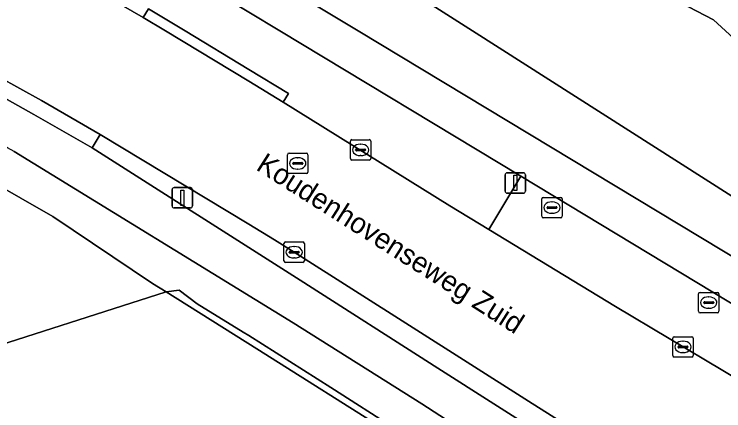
# Model space of a CAD drawing. Extents: x 162879 to 165540, y 384011 to 385181.
# Drawn here: x 163988.52 to 164023.23, y 384481.4 to 384500.81 of the extents above; entities that cross this region are included whole.
import ezdxf

# ---------------------------------------------------------------- set-up
doc = ezdxf.new("R2010")
doc.units = 0
for name, color, linetype in [('IMGEO_Erf', 7, 'Continuous'), ('IMGEO_Fietspad_gesloten', 7, 'Continuous'), ('IMGEO_Fietspad_open', 7, 'Continuous'), ('IMGEO_Gemengd_bos', 7, 'Continuous'), ('IMGEO_Groenvoorziening', 7, 'Continuous'), ('IMGEO_Hek', 7, 'Continuous'), ('IMGEO_Kolk', 7, 'Continuous'), ('IMGEO_Lichtmast', 7, 'Continuous'), ('IMGEO_Openbare_ruimte_label', 7, 'Continuous'), ('IMGEO_Pand', 7, 'Continuous'), ('IMGEO_Rijbaan_lokaal_gesloten', 7, 'Continuous'), ('IMGEO_Rioolput', 7, 'Continuous'), ('IMGEO_Verkeerseiland_open', 7, 'Continuous'), ('IMGEO_Verkeersregelinstallatiepaal', 7, 'Continuous'), ('IMGEO_Voetpad_open', 7, 'Continuous')]:
    doc.layers.add(name, color=color, linetype=linetype)

msp = doc.modelspace()

# ---------------------------------------------------------------- linework, layer by layer
at = {"layer": 'IMGEO_Erf'}
for points in [[(163977.102, 384518.017), (163999.855, 384507.078), (164000, 384506.985), (164010.947, 384500), (164040.047, 384481.433)], [(164075.059, 384483.197), (164073.692, 384484.761), (164077.391, 384488.124), (164071.515, 384492.449), (164068.483, 384490.058), (164069.655, 384486.192), (164069.193, 384486.039), (164069.32, 384485.578), (164065.977, 384484.533), (164065.378, 384486.451), (164059.412, 384484.592), (164050.462, 384484.232), (164041.668, 384486.233), (164033.747, 384490.379), (164023.311, 384500), (164022.729, 384500.537), (164017.458, 384503.291)], [(164024.324, 384464.783), (164007.922, 384479.696), (164007.065, 384480.235), (164000.388, 384484.433), (163995.958, 384487.218), (163986.076, 384484.053), (163967.218, 384478.066), (163952.026, 384473.244)]]:
    msp.add_lwpolyline(points, dxfattribs=at)
at = {"layer": 'IMGEO_Fietspad_gesloten'}
for points in [[(164038.87, 384479.774), (164005.351, 384500), (164000, 384503.229), (163995.542, 384505.919)], [(163992.18, 384505.608), (163994.613, 384504.172), (164000, 384500.919), (164001.522, 384500), (164013.311, 384492.88), (164028.96, 384483.428), (164037.825, 384478.074)]]:
    msp.add_lwpolyline(points, dxfattribs=at)
at = {"layer": 'IMGEO_Fietspad_open'}
for points in [[(164046.321, 384458.236), (164042.366, 384461.222), (164038.409, 384464.101), (164035.588, 384466.084), (164032.884, 384467.984), (164023.539, 384474.332), (164017.469, 384478.249), (164009.245, 384483.486), (164002.517, 384487.804), (163992.332, 384494.269), (163989.491, 384495.908), (163987.373, 384497.08), (163985.254, 384498.25), (163981.926, 384500), (163973.063, 384504.482), (163968.811, 384506.572), (163936.739, 384522.254)], [(163988.523, 384494.089), (164002.175, 384485.703), (164008.463, 384481.739), (164014.169, 384478.04), (164019.234, 384474.701), (164024.613, 384471.195), (164033.02, 384465.475), (164033.514, 384465.131), (164034.007, 384464.787)]]:
    msp.add_lwpolyline(points, dxfattribs=at)
msp.add_arc((163856.777, 384268.47), 261.268, 59.71804, 62.39691, dxfattribs=at)
at = {"layer": 'IMGEO_Gemengd_bos'}
msp.add_lwpolyline([(163943.494, 384482.414), (163944.929, 384476.199), (163938.963, 384474.249), (163933.363, 384469.485), (163922.095, 384461.981), (163922.323, 384455.925), (163952.519, 384470.865), (163953.09, 384471.066), (163952.736, 384471.79), (163952.026, 384473.244), (163967.218, 384478.066), (163986.076, 384484.053), (163995.958, 384487.218), (163995.289, 384487.639), (163990.412, 384490.908), (163987.273, 384492.711), (163977.777, 384489.802), (163954.868, 384485.471)], close=True, dxfattribs=at)
at = {"layer": 'IMGEO_Groenvoorziening'}
msp.add_lwpolyline([(164000, 384485.086), (163999.731, 384485.257), (163997.466, 384486.631), (163996.593, 384487.314), (163995.958, 384487.218), (164000.388, 384484.433), (164007.065, 384480.235), (164007.231, 384480.492), (164004.004, 384482.542)], close=True, dxfattribs=at)
at = {"layer": 'IMGEO_Hek'}
msp.add_lwpolyline([(163986.076, 384484.053), (163995.958, 384487.218)], dxfattribs=at)
at = {"layer": 'IMGEO_Kolk'}
for p, q in [((164005.042, 384494.673), (164005.894, 384494.673)), ((164004.967, 384493.747), (164004.967, 384494.599)), ((164005.455, 384494.453), (164005.48, 384494.453)), ((164005.968, 384494.599), (164005.968, 384493.747)), ((164005.226, 384494.167), (164005.226, 384494.179)), ((164005.664, 384494.13), (164005.266, 384494.13)), ((164005.269, 384494.216), (164005.667, 384494.216)), ((164005.71, 384494.179), (164005.71, 384494.167)), ((164005.894, 384493.673), (164005.042, 384493.673)), ((164005.478, 384493.893), (164005.453, 384493.893)), ((164014.405, 384491.848), (164015.257, 384491.848)), ((164014.33, 384490.922), (164014.33, 384491.774)), ((164014.818, 384491.628), (164014.843, 384491.628)), ((164015.331, 384491.774), (164015.331, 384490.922)), ((164014.589, 384491.342), (164014.589, 384491.354)), ((164015.027, 384491.305), (164014.629, 384491.305)), ((164014.632, 384491.391), (164015.03, 384491.391)), ((164015.073, 384491.354), (164015.073, 384491.342)), ((164015.257, 384490.848), (164014.405, 384490.848)), ((164014.841, 384491.068), (164014.816, 384491.068)), ((164001.718, 384488.739), (164001.718, 384489.591)), ((164001.793, 384489.665), (164002.645, 384489.665)), ((164002.206, 384489.445), (164002.231, 384489.445)), ((164002.719, 384489.591), (164002.719, 384488.739)), ((164001.977, 384489.159), (164001.977, 384489.171)), ((164002.415, 384489.122), (164002.017, 384489.122)), ((164002.02, 384489.208), (164002.418, 384489.208)), ((164002.461, 384489.171), (164002.461, 384489.159)), ((164002.229, 384488.885), (164002.204, 384488.885)), ((164002.645, 384488.665), (164001.793, 384488.665)), ((164021.996, 384486.273), (164021.996, 384487.125)), ((164022.071, 384487.199), (164022.923, 384487.199)), ((164022.997, 384487.125), (164022.997, 384486.273)), ((164022.255, 384486.693), (164022.255, 384486.705)), ((164022.693, 384486.656), (164022.295, 384486.656)), ((164022.298, 384486.742), (164022.696, 384486.742)), ((164022.484, 384486.979), (164022.509, 384486.979)), ((164022.739, 384486.705), (164022.739, 384486.693)), ((164022.507, 384486.419), (164022.482, 384486.419)), ((164022.923, 384486.199), (164022.071, 384486.199)), ((164020.736, 384484.105), (164020.736, 384484.957)), ((164020.811, 384485.031), (164021.663, 384485.031)), ((164021.737, 384484.957), (164021.737, 384484.105)), ((164021.038, 384484.574), (164021.436, 384484.574)), ((164021.224, 384484.811), (164021.249, 384484.811)), ((164020.995, 384484.525), (164020.995, 384484.537)), ((164021.433, 384484.488), (164021.035, 384484.488)), ((164021.247, 384484.251), (164021.222, 384484.251)), ((164021.479, 384484.537), (164021.479, 384484.525)), ((164021.663, 384484.031), (164020.811, 384484.031))]:
    msp.add_line(p, q, dxfattribs=at)
for points in [[(164005.042, 384494.673), (164005.894, 384494.673)], [(164004.967, 384493.747), (164004.967, 384494.599)], [(164005.968, 384494.599), (164005.968, 384493.747)], [(164005.894, 384493.673), (164005.042, 384493.673)], [(164014.405, 384491.848), (164015.257, 384491.848)], [(164014.33, 384490.922), (164014.33, 384491.774)], [(164015.331, 384491.774), (164015.331, 384490.922)], [(164015.257, 384490.848), (164014.405, 384490.848)], [(164001.718, 384488.739), (164001.718, 384489.591)], [(164001.793, 384489.665), (164002.645, 384489.665)], [(164002.719, 384489.591), (164002.719, 384488.739)], [(164002.645, 384488.665), (164001.793, 384488.665)], [(164021.996, 384486.273), (164021.996, 384487.125)], [(164022.071, 384487.199), (164022.923, 384487.199)], [(164022.997, 384487.125), (164022.997, 384486.273)], [(164022.923, 384486.199), (164022.071, 384486.199)], [(164020.736, 384484.105), (164020.736, 384484.957)], [(164020.811, 384485.031), (164021.663, 384485.031)], [(164021.737, 384484.957), (164021.737, 384484.105)], [(164021.663, 384484.031), (164020.811, 384484.031)]]:
    msp.add_lwpolyline(points, dxfattribs=at)
for centre, radius, start, end in [((164005.044, 384494.597), 0.0765, 91.552, 178.448), ((164005.044, 384494.597), 0.0765, 91.552, 178.448), ((164005.892, 384494.597), 0.0765, 1.552, 88.448), ((164005.892, 384494.597), 0.0765, 1.552, 88.448), ((164005.266, 384494.176), 0.0403, 85.8775, 175.7526), ((164005.263, 384494.166), 0.0366, 178.938, 274.7102), ((164005.667, 384494.173), 0.043, 264.8664, 352.4533), ((164005.671, 384494.178), 0.0386, 1.7309, 96.639), ((164005.044, 384493.749), 0.0765, 181.552, 268.448), ((164005.044, 384493.749), 0.0765, 181.552, 268.448), ((164005.892, 384493.749), 0.0765, 271.552, 358.448), ((164005.892, 384493.749), 0.0765, 271.552, 358.448), ((164014.407, 384491.772), 0.0765, 91.552, 178.448), ((164014.407, 384491.772), 0.0765, 91.552, 178.448), ((164015.255, 384491.772), 0.0765, 1.552, 88.448), ((164015.255, 384491.772), 0.0765, 1.552, 88.448), ((164014.629, 384491.351), 0.0403, 85.8775, 175.7526), ((164014.626, 384491.341), 0.0366, 178.938, 274.7102), ((164015.03, 384491.348), 0.043, 264.8664, 352.4533), ((164015.034, 384491.353), 0.0386, 1.7309, 96.639), ((164014.407, 384490.924), 0.0765, 181.552, 268.448), ((164014.407, 384490.924), 0.0765, 181.552, 268.448), ((164015.255, 384490.924), 0.0765, 271.552, 358.448), ((164015.255, 384490.924), 0.0765, 271.552, 358.448), ((164001.795, 384489.589), 0.0765, 91.552, 178.448), ((164001.795, 384489.589), 0.0765, 91.552, 178.448), ((164002.643, 384489.589), 0.0765, 1.552, 88.448), ((164002.643, 384489.589), 0.0765, 1.552, 88.448), ((164002.017, 384489.168), 0.0403, 85.8775, 175.7526), ((164002.014, 384489.158), 0.0366, 178.938, 274.7102), ((164002.418, 384489.165), 0.043, 264.8664, 352.4533), ((164002.422, 384489.17), 0.0386, 1.7309, 96.639), ((164001.795, 384488.741), 0.0765, 181.552, 268.448), ((164001.795, 384488.741), 0.0765, 181.552, 268.448), ((164002.643, 384488.741), 0.0765, 271.552, 358.448), ((164002.643, 384488.741), 0.0765, 271.552, 358.448), ((164022.073, 384487.123), 0.0765, 91.552, 178.448), ((164022.073, 384487.123), 0.0765, 91.552, 178.448), ((164022.921, 384487.123), 0.0765, 1.552, 88.448), ((164022.921, 384487.123), 0.0765, 1.552, 88.448), ((164022.295, 384486.702), 0.0403, 85.8775, 175.7526), ((164022.292, 384486.692), 0.0366, 178.938, 274.7102), ((164022.696, 384486.699), 0.043, 264.8664, 352.4533), ((164022.7, 384486.704), 0.0386, 1.7309, 96.639), ((164022.073, 384486.275), 0.0765, 181.552, 268.448), ((164022.073, 384486.275), 0.0765, 181.552, 268.448), ((164022.921, 384486.275), 0.0765, 271.552, 358.448), ((164022.921, 384486.275), 0.0765, 271.552, 358.448), ((164020.813, 384484.955), 0.0765, 91.552, 178.448), ((164020.813, 384484.955), 0.0765, 91.552, 178.448), ((164021.661, 384484.955), 0.0765, 1.552, 88.448), ((164021.661, 384484.955), 0.0765, 1.552, 88.448), ((164021.035, 384484.534), 0.0403, 85.8775, 175.7526), ((164021.44, 384484.536), 0.0386, 1.7309, 96.639), ((164021.032, 384484.524), 0.0366, 178.938, 274.7102), ((164021.436, 384484.531), 0.043, 264.8664, 352.4533), ((164020.813, 384484.107), 0.0765, 181.552, 268.448), ((164020.813, 384484.107), 0.0765, 181.552, 268.448), ((164021.661, 384484.107), 0.0765, 271.552, 358.448), ((164021.661, 384484.107), 0.0765, 271.552, 358.448)]:
    msp.add_arc(centre, radius, start, end, dxfattribs=at)
for centre, major_axis, ratio, start_param, end_param in [((164005.454, 384494.173), (-0.387, 0.002), 0.722429, 4.712389, 7.853982), ((164005.479, 384494.173), (-0.39, 0.002), 0.717154, 1.570796, 4.712389), ((164014.817, 384491.348), (-0.387, 0.002), 0.722429, 4.712389, 7.853982), ((164014.842, 384491.348), (-0.39, 0.002), 0.717154, 1.570796, 4.712389), ((164002.205, 384489.165), (-0.387, 0.002), 0.722429, 4.712389, 7.853982), ((164002.23, 384489.165), (-0.39, 0.002), 0.717154, 1.570796, 4.712389), ((164022.483, 384486.699), (-0.387, 0.002), 0.722429, 4.712389, 7.853982), ((164022.508, 384486.699), (-0.39, 0.002), 0.717154, 1.570796, 4.712389), ((164021.223, 384484.531), (-0.387, 0.002), 0.722429, 4.712389, 7.853982), ((164021.248, 384484.531), (-0.39, 0.002), 0.717154, 1.570796, 4.712389)]:
    msp.add_ellipse(centre, major_axis=major_axis, ratio=ratio, start_param=start_param, end_param=end_param, dxfattribs=at)
at = {"layer": 'IMGEO_Lichtmast'}
for p, q in [((164012.539, 384492.154), (164012.539, 384492.954)), ((164012.539, 384492.954), (164012.539, 384492.154)), ((164012.639, 384493.054), (164013.429, 384493.054)), ((164013.429, 384493.054), (164012.639, 384493.054)), ((164013.529, 384492.954), (164013.529, 384492.154)), ((164013.529, 384492.154), (164013.529, 384492.954)), ((164013.429, 384492.054), (164012.639, 384492.054)), ((164012.639, 384492.054), (164013.429, 384492.054))]:
    msp.add_line(p, q, dxfattribs=at)
msp.add_lwpolyline([(164012.959, 384492.929), (164013.109, 384492.929), (164013.109, 384492.179), (164012.959, 384492.179), (164012.959, 384492.929)], dxfattribs=at)
for centre, start, end in [((164012.639, 384492.954), 90, 180), ((164012.639, 384492.954), 90, 180), ((164013.429, 384492.954), 0, 90), ((164013.429, 384492.954), 360, 90), ((164012.639, 384492.154), 180, 270), ((164012.639, 384492.154), 180, 270), ((164013.429, 384492.154), 270, 0), ((164013.429, 384492.154), 270, 0)]:
    msp.add_arc(centre, 0.1, start, end, dxfattribs=at)
at = {"layer": 'IMGEO_Pand'}
msp.add_lwpolyline([(164016.214, 384517.208), (164012.723, 384517.977), (164012.654, 384517.699), (164011.47, 384504.631), (164017.458, 384503.291), (164022.729, 384500.537), (164023.311, 384500), (164033.747, 384490.379), (164041.668, 384486.233), (164050.462, 384484.232), (164059.412, 384484.592), (164065.378, 384486.451), (164068.122, 384487.306), (164064.213, 384495.741), (164063.298, 384497.716), (164060.418, 384496.852), (164057.285, 384495.913), (164051.417, 384495.675), (164045.661, 384497.005), (164040.316, 384499.798), (164040.097, 384500), (164029.381, 384509.883), (164021.411, 384514.078), (164015.767, 384515.348)], close=True, dxfattribs=at)
at = {"layer": 'IMGEO_Rijbaan_lokaal_gesloten'}
for points in [[(163995.929, 384500), (163994.837, 384500.657), (163993.098, 384501.663), (163984.732, 384506.155), (163979.331, 384508.918), (163974.085, 384511.506)], [(163973.418, 384505.188), (163983.595, 384500), (163984.601, 384499.47), (163985.606, 384498.938), (163989.857, 384496.589), (163991.292, 384495.761), (163992.726, 384494.93), (164000, 384490.544), (164001.25, 384489.769), (164002.215, 384489.166), (164013.679, 384481.878), (164017.799, 384479.262), (164023.635, 384475.41), (164032.788, 384469.565), (164033.634, 384469.031), (164036.406, 384467.296), (164039.06, 384465.555), (164042.902, 384472.332), (164040.84, 384473.302), (164039.207, 384474.193)], [(164025.807, 384481.815), (164017.936, 384486.504), (164011.737, 384490.275), (164009.838, 384491.43), (164001.677, 384496.502), (164000, 384497.529), (163995.929, 384500)]]:
    msp.add_lwpolyline(points, dxfattribs=at)
at = {"layer": 'IMGEO_Rioolput'}
for p, q in [((164001.892, 384493.085), (164001.892, 384493.937)), ((164001.967, 384494.011), (164002.819, 384494.011)), ((164002.893, 384493.937), (164002.893, 384493.085)), ((164002.38, 384493.791), (164002.405, 384493.791)), ((164002.151, 384493.505), (164002.151, 384493.517)), ((164002.589, 384493.468), (164002.191, 384493.468)), ((164002.194, 384493.554), (164002.592, 384493.554)), ((164002.403, 384493.231), (164002.378, 384493.231)), ((164002.635, 384493.517), (164002.635, 384493.505)), ((164002.819, 384493.011), (164001.967, 384493.011))]:
    msp.add_line(p, q, dxfattribs=at)
for points in [[(164001.892, 384493.085), (164001.892, 384493.937)], [(164001.967, 384494.011), (164002.819, 384494.011)], [(164002.893, 384493.937), (164002.893, 384493.085)], [(164002.819, 384493.011), (164001.967, 384493.011)]]:
    msp.add_lwpolyline(points, dxfattribs=at)
for centre, radius, start, end in [((164001.969, 384493.935), 0.0765, 91.552, 178.448), ((164001.969, 384493.935), 0.0765, 91.552, 178.448), ((164002.817, 384493.935), 0.0765, 1.552, 88.448), ((164002.817, 384493.935), 0.0765, 1.552, 88.448), ((164002.191, 384493.514), 0.0403, 85.8775, 175.7526), ((164002.188, 384493.504), 0.0366, 178.938, 274.7102), ((164002.592, 384493.511), 0.043, 264.8664, 352.4533), ((164002.596, 384493.516), 0.0386, 1.7309, 96.639), ((164001.969, 384493.087), 0.0765, 181.552, 268.448), ((164001.969, 384493.087), 0.0765, 181.552, 268.448), ((164002.817, 384493.087), 0.0765, 271.552, 358.448), ((164002.817, 384493.087), 0.0765, 271.552, 358.448)]:
    msp.add_arc(centre, radius, start, end, dxfattribs=at)
for centre, major_axis, ratio, start_param, end_param in [((164002.379, 384493.511), (-0.387, 0.002), 0.722429, 4.712389, 7.853982), ((164002.404, 384493.511), (-0.39, 0.002), 0.717154, 1.570796, 4.712389)]:
    msp.add_ellipse(centre, major_axis=major_axis, ratio=ratio, start_param=start_param, end_param=end_param, dxfattribs=at)
at = {"layer": 'IMGEO_Verkeerseiland_open'}
for points in [[(164001.522, 384500), (164000, 384500.919), (163994.613, 384504.172), (163992.18, 384505.608)], [(163993.098, 384501.663), (163994.837, 384500.657), (163995.096, 384501.084), (163996.88, 384500), (164000, 384498.105), (164001.936, 384496.929), (164001.677, 384496.502), (164009.838, 384491.43), (164011.737, 384490.275), (164013.311, 384492.88), (164001.522, 384500)]]:
    msp.add_lwpolyline(points, dxfattribs=at)
msp.add_lwpolyline([(164013.679, 384481.878), (164002.215, 384489.166), (164001.25, 384489.769), (164000, 384490.544), (163992.726, 384494.93), (163992.332, 384494.269), (164002.517, 384487.804), (164009.245, 384483.486), (164017.469, 384478.249), (164023.539, 384474.332), (164032.884, 384467.984), (164035.588, 384466.084), (164038.409, 384464.101), (164042.366, 384461.222), (164043.475, 384462.746), (164039.06, 384465.555), (164036.406, 384467.296), (164033.634, 384469.031), (164032.788, 384469.565), (164023.635, 384475.41), (164017.799, 384479.262)], close=True, dxfattribs=at)
at = {"layer": 'IMGEO_Verkeersregelinstallatiepaal'}
for p, q in [((163996.249, 384491.431), (163996.249, 384492.231)), ((163996.249, 384492.231), (163996.249, 384491.431)), ((163996.349, 384492.331), (163997.139, 384492.331)), ((163997.139, 384492.331), (163996.349, 384492.331)), ((163997.239, 384492.231), (163997.239, 384491.431)), ((163997.239, 384491.431), (163997.239, 384492.231)), ((163997.139, 384491.331), (163996.349, 384491.331)), ((163996.349, 384491.331), (163997.139, 384491.331))]:
    msp.add_line(p, q, dxfattribs=at)
msp.add_lwpolyline([(163996.669, 384492.206), (163996.819, 384492.206), (163996.819, 384491.456), (163996.669, 384491.456), (163996.669, 384492.206)], dxfattribs=at)
for centre, start, end in [((163996.349, 384492.231), 90, 180), ((163996.349, 384492.231), 90, 180), ((163997.139, 384492.231), 0, 90), ((163997.139, 384492.231), 360, 90), ((163996.349, 384491.431), 180, 270), ((163996.349, 384491.431), 180, 270), ((163997.139, 384491.431), 270, 0), ((163997.139, 384491.431), 270, 0)]:
    msp.add_arc(centre, 0.1, start, end, dxfattribs=at)
at = {"layer": 'IMGEO_Voetpad_open'}
for points in [[(164040.047, 384481.433), (164010.947, 384500), (164000, 384506.985), (163999.855, 384507.078), (163977.102, 384518.017)], [(163995.542, 384505.919), (164000, 384503.229), (164005.351, 384500), (164038.87, 384479.774)], [(164034.007, 384464.787), (164033.514, 384465.131), (164033.02, 384465.475), (164024.613, 384471.195), (164019.234, 384474.701), (164014.169, 384478.04), (164008.463, 384481.739), (164002.175, 384485.703), (163988.523, 384494.089)], [(163987.273, 384492.711), (163990.412, 384490.908), (163995.289, 384487.639), (163995.958, 384487.218), (163996.593, 384487.314), (163997.466, 384486.631), (163999.731, 384485.257), (164000, 384485.086), (164004.004, 384482.542), (164007.231, 384480.492), (164011.172, 384477.988), (164015.292, 384475.308), (164019.201, 384472.707), (164025.612, 384468.333), (164024.366, 384464.898), (164024.324, 384464.783), (164026.394, 384462.901), (164026.512, 384462.958), (164028.499, 384463.91)], [(164013.311, 384492.88), (164011.737, 384490.275), (164017.936, 384486.504), (164025.807, 384481.815)], [(164027.414, 384480.869), (164028.96, 384483.428), (164013.311, 384492.88)]]:
    msp.add_lwpolyline(points, dxfattribs=at)
for points in [[(164001.677, 384496.502), (164001.936, 384496.929), (164000, 384498.105), (163996.88, 384500), (163995.096, 384501.084), (163994.837, 384500.657), (163995.929, 384500), (164000, 384497.529)], [(163985.254, 384498.25), (163987.373, 384497.08), (163989.491, 384495.908), (163992.332, 384494.269), (163992.726, 384494.93), (163991.292, 384495.761), (163989.857, 384496.589), (163985.606, 384498.938)]]:
    msp.add_lwpolyline(points, close=True, dxfattribs=at)
msp.add_arc((163856.777, 384268.47), 261.268, 59.71804, 62.39691, dxfattribs=at)

# ---------------------------------------------------------------- texts
at = {"layer": 'IMGEO_Openbare_ruimte_label'}
msp.add_text('Koudenhovenseweg Zuid', height=1, rotation=327.5332, dxfattribs=at).set_placement((164000.303, 384493.231))

doc.saveas('drawing.dxf')
